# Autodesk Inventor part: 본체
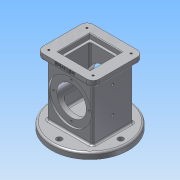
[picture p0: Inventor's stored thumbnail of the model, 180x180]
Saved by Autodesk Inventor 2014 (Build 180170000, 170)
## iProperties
Created: 2018-10
Part Number: 본체
Material: 알루미늄 6061
Document SubType Name: Modeling
Designer: Administrator
Density: 2.71 g/cm^3
Appearance: 알루미늄 - 평지
Mass: 988.221 g
Surface Area: 743.905 cm^2
Volume: 364.657 cm^3
Author: Administrator
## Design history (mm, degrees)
sketch "스케치1"
  geometry: L1 (-37, -33)-(37, -33); L2 (37, -33)-(37, 33); L3 (37, 33)-(-37, 33); L4 (-37, 33)-(-37, -33); L5 (-37, -33)-(37, 33); L6 (37, -33)-(-37, 33); 1 further point
  constraints: 12 end point, 2 midpoint, 2 parallel, 1 horizontal, 1 perpendicular
  dimensions: "d0" = 74 distance of L2.end L3.end; "d1" = 66 distance of L1.end L2.end
extrude "돌출1" new body sketch "스케치1" distance "d2" = 88; taper "d3" = 0 deg
sketch "스케치2"
  geometry: C1 r 62.5 at (0, 0); 1 further point
  constraints: 1 centre point, 1 coincident
  dimensions: "d4" = 125 diameter of C1
extrude "돌출2" join sketch "스케치2" distance "d5" = 10; taper "d6" = 0 deg
sketch "스케치3"
  geometry: L1 (-46, -41)-(46, -41); L2 (46, -41)-(46, 41); L3 (46, 41)-(-46, 41); L4 (-46, 41)-(-46, -41); L5 (-46, -41)-(46, 41); L6 (46, -41)-(-46, 41); 1 further point
  constraints: 12 end point, 2 midpoint, 2 parallel, 1 horizontal, 1 perpendicular
  dimensions: "d7" = 92 distance of L2.end L3.end; "d8" = 82 distance of L1.end L2.end
extrude "돌출3" join sketch "스케치3" distance "d9" = 10; taper "d10" = 0 deg
fillet "모깎기1" dims "d11" = 10
sketch "스케치4"
  geometry: L1 (0, 0)-(74, 0) reference; L2 (-25.5, -10)-(99.5, -10) reference; C1 r 35 at (37, 44); 2 further points
  constraints: 1 centre point, 1 midpoint, 1 vertical alignment
  dimensions: "d12" = 70 diameter of C1; "d13" = 54 distance from line of L2 C1.centre
extrude "돌출4" cut sketch "스케치4" distance "d14" = 3; taper "d15" = 0 deg
sketch "스케치5"
  geometry: C1 r 35 at (0, 0) reference; C2 r 24 at (0, 0); 1 further point
  constraints: 1 centre point, 1 coincident
  dimensions: "d16" = 48 diameter of C2
extrude "돌출5" cut sketch "스케치5" stored distance "d17" = 3; taper "d18" = 0 deg
sketch "스케치6" dims "d19" = 58
  geometry: C1 r 24 at (0, 0) reference; C2 r 35 at (0, 0) reference; 3 further points
  constraints: 2 vertical alignment, 1 coincident, 2 other
hole "구멍1" sketch "스케치6" at (0, 29) diameter "d20" = 3.242; stored, may be unused: countersink angle "d24" = 90 deg, drill point angle "d26" = 118 deg; dims "d21" = 4, "d22" = 4, "d23" = 2, "d25" = 6
sketch "스케치7"
  geometry: L1 (-26, -26)-(26, -26); L2 (26, -26)-(26, 26); L3 (26, 26)-(-26, 26); L4 (-26, 26)-(-26, -26); L5 (-26, -26)-(26, 26); L6 (26, -26)-(-26, 26); 1 further point
  constraints: 12 end point, 2 midpoint, 2 parallel, 1 horizontal, 1 perpendicular
  dimensions: "d30" = 52 distance of L2.end L3.end; "d31" = 52 distance of L1.end L2.end
extrude "돌출6" cut sketch "스케치7" distance "d32" = 8; taper "d33" = 0 deg
sketch "스케치8"
  geometry: L1 (-22, -22)-(22, -22); L2 (22, -22)-(22, 22); L3 (22, 22)-(-22, 22); L4 (-22, 22)-(-22, -22); L5 (-22, -22)-(22, 22); L6 (22, -22)-(-22, 22); 1 further point
  constraints: 12 end point, 2 midpoint, 2 parallel, 1 horizontal, 1 perpendicular
  dimensions: "d34" = 44 distance of L2.end L3.end; "d35" = 44 distance of L1.end L2.end
extrude "돌출7" cut sketch "스케치8" distance "d36" = 74; taper "d37" = 0 deg
sketch "스케치9"
  geometry: C1 r 62.5 at (0, 0) reference; C2 r 28 at (0, 0)
  constraints: 1 centre point, 1 coincident
  dimensions: "d38" = 56 diameter of C2
extrude "돌출8" cut sketch "스케치9" distance "d39" = 18; taper "d40" = -10 deg
sketch "스케치10" dims "d41" = 100
  geometry: C1 r 28 at (0, 0) reference; C2 r 62.5 at (0, 0) reference; 2 further points
  constraints: 2 vertical alignment, 1 coincident, 2 other
hole "구멍2" sketch "스케치10" at (0, 50) diameter "d42" = 9; stored, may be unused: countersink angle "d46" = 90 deg, drill point angle "d48" = 118 deg; dims "d43" = 4, "d44" = 4, "d45" = 2, "d47" = 6
hole "구멍3" diameter "d54" = 3.242; stored, may be unused: countersink angle "d58" = 90 deg, drill point angle "d60" = 118 deg; dims "d52" = 10, "d53" = 10, "d55" = 4, "d56" = 4, "d57" = 2, "d59" = 6
hole "구멍4" diameter "d63" = 3.242; stored, may be unused: countersink angle "d67" = 90 deg, drill point angle "d69" = 118 deg; dims "d61" = 10, "d62" = 10, "d64" = 4, "d65" = 4, "d66" = 2, "d68" = 6
hole "구멍5" diameter "d72" = 3.242; stored, may be unused: countersink angle "d76" = 90 deg, drill point angle "d78" = 118 deg; dims "d70" = 10, "d71" = 10, "d73" = 4, "d74" = 4, "d75" = 2, "d77" = 6
hole "구멍6" diameter "d81" = 3.242; stored, may be unused: countersink angle "d85" = 90 deg, drill point angle "d87" = 118 deg; dims "d79" = 10, "d80" = 10, "d82" = 4, "d83" = 4, "d84" = 2, "d86" = 6
fillet "모깎기2" dims "d89" = 3
sketch "스케치12"
  geometry: L1 (72, -7)-(0, -7) reference; L2 (-10, 0)-(-10, -7) reference; 2 further points
  constraints: 1 other
  dimensions: "d90" = 46 distance from line of L2 point (36, -3); "d91" = 4 distance from line of L1 point (36, -3)
feature "엠보싱1" sketch "스케치12" dims "d0" = 74, "d1" = 66, "d92" = 0.5, "d93" = 0
sketch "스케치13"
  geometry: L1 (0, 0)-(66, 0) reference; L2 (0, 0)-(0, 88) reference; L3 (33, 27)-(33, 70); L4 (-29.5, -10)-(95.5, -10) reference; 4 further points
  constraints: 2 coincident, 2 end point, 1 midpoint, 1 parallel, 1 vertical alignment
  dimensions: "d94" = 37 distance from line of L4 L3.start; "d95" = 43 distance of L3.start L3.end
hole "구멍7" sketch "스케치13" at (33, 27), (33, 70) diameter "d96" = 4.134; stored, may be unused: countersink angle "d100" = 90 deg, drill point angle "d102" = 118 deg; dims "d97" = 4, "d98" = 4, "d99" = 2, "d101" = 20
fillet "모깎기3" dims "d103" = 3
fillet "모깎기4" dims "d104" = 3
fillet "모깎기5" dims "d105" = 3
chamfer "모따기1" distance "d106" = 1; stored, may be unused: second distance "d107" = 2, angle "d108" = 45 deg
fillet "모깎기6" dims "d109" = 3
node "솔리드1"
mirror "대칭1"
pattern_circular "원형 패턴1" dims angle "d28" = 360 deg
mirror "대칭2"
pattern_circular "원형 패턴2" dims angle "d50" = 360 deg
